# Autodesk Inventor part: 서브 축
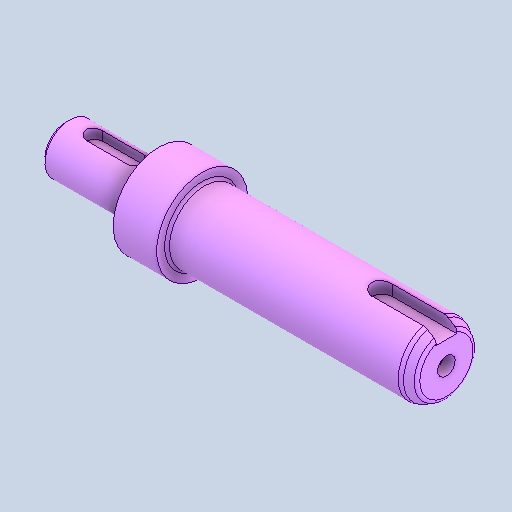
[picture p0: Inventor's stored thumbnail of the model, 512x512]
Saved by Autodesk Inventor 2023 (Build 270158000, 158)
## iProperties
Created: 2025-04
Part Number: 서브 축
Material: 강철, 탄소
Document SubType Name: Modeling
Designer: ADMIN_PC
Density: 7.85 g/cm^3
Appearance: 기본값
Author: jhkim
Sending System: Autodesk Inventor 2026
Preprocessor: ST-DEVELOPER v20.1
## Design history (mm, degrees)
feature "솔리드1"
node "솔리드2"
